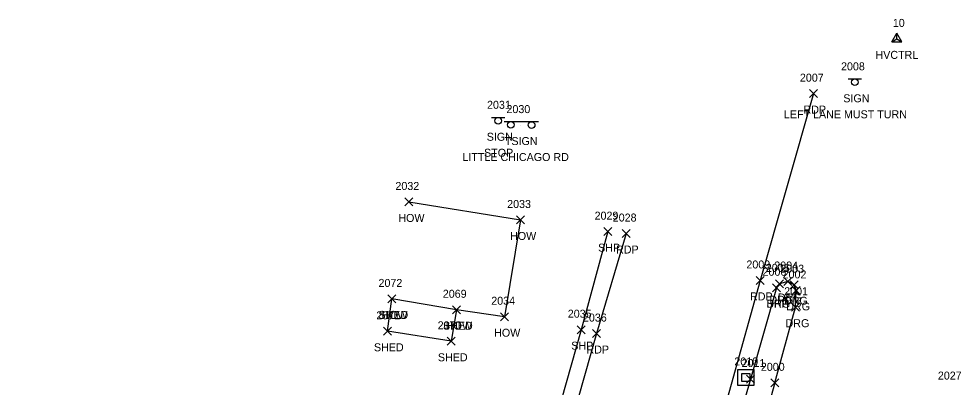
# Model space of a CAD drawing. Extents: x 1443071 to 1445292, y 614024 to 622563.
# Drawn here: x 1444555.8 to 1444791.3, y 622470.6 to 622562.9 of the extents above; entities that cross this region are included whole.
import ezdxf

# ---------------------------------------------------------------- set-up
doc = ezdxf.new("R2010")
doc.units = 0
for name, color, linetype in [('C_A', 7, 'Continuous'), ('C_I', 7, 'Continuous'), ('CPSM', 7, 'Continuous'), ('D_I', 7, 'Continuous'), ('DS', 7, 'Continuous'), ('L_A', 7, 'Continuous'), ('L_I', 7, 'Continuous'), ('L_TIC', 7, 'Continuous'), ('LBC', 7, 'Continuous'), ('P_A', 7, 'Continuous'), ('P_I', 7, 'Continuous'), ('P_TIC', 7, 'Continuous'), ('PET', 7, 'Continuous'), ('PSP', 7, 'Continuous'), ('R_A', 7, 'Continuous'), ('R_I', 7, 'Continuous'), ('R_TIC', 7, 'Continuous'), ('RDG', 7, 'Continuous'), ('S_A', 7, 'Continuous'), ('S_C', 7, 'Continuous'), ('S_I', 7, 'Continuous'), ('SSGN', 7, 'Continuous')]:
    doc.layers.add(name, color=color, linetype=linetype)

msp = doc.modelspace()

# ---------------------------------------------------------------- linework, layer by layer
at = {"layer": 'CPSM'}
for p, q in [((1444773.97, 622557.11), (1444775.22, 622559.27)), ((1444773.97, 622557.11), (1444775.22, 622557.83)), ((1444776.47, 622557.11), (1444775.22, 622559.27)), ((1444775.22, 622557.83), (1444775.22, 622559.27)), ((1444775.22, 622557.83), (1444775.22, 622557.83)), ((1444775.22, 622557.83), (1444776.47, 622557.11)), ((1444773.97, 622557.11), (1444776.47, 622557.11))]:
    msp.add_line(p, q, dxfattribs=at)
at = {"layer": 'DS'}
for p, q in [((1444735.49, 622475.09), (1444739.49, 622475.09)), ((1444735.49, 622471.09), (1444735.49, 622475.09)), ((1444736.49, 622472.09), (1444736.49, 622474.09)), ((1444736.49, 622474.09), (1444738.49, 622474.09)), ((1444737.5, 622473.09), (1444737.5, 622473.09)), ((1444737.5, 622473.09), (1444737.5, 622473.09)), ((1444738.49, 622474.09), (1444738.49, 622472.09)), ((1444739.49, 622475.09), (1444739.49, 622471.09)), ((1444739.49, 622471.09), (1444735.49, 622471.09)), ((1444738.49, 622472.09), (1444736.49, 622472.09))]:
    msp.add_line(p, q, dxfattribs=at)
at = {"layer": 'L_TIC'}
for points in [[(1444652.28, 622516.01), (1444654.28, 622518.01)], [(1444654.28, 622516.01), (1444652.28, 622518.01)], [(1444680.2, 622511.5), (1444682.2, 622513.5)], [(1444682.2, 622511.5), (1444680.2, 622513.5)], [(1444648.05, 622491.74), (1444650.05, 622493.74)], [(1444650.05, 622491.74), (1444648.05, 622493.74)], [(1444648.05, 622491.74), (1444650.05, 622493.74)], [(1444650.05, 622491.74), (1444648.05, 622493.74)], [(1444664.18, 622489.03), (1444666.18, 622491.03)], [(1444666.18, 622489.03), (1444664.18, 622491.03)], [(1444664.18, 622489.03), (1444666.18, 622491.03)], [(1444666.18, 622489.03), (1444664.18, 622491.03)], [(1444676.23, 622487.28), (1444678.23, 622489.28)], [(1444678.23, 622487.28), (1444676.23, 622489.28)], [(1444646.93, 622483.63), (1444648.93, 622485.63)], [(1444648.93, 622483.63), (1444646.93, 622485.63)], [(1444662.91, 622481.13), (1444664.91, 622483.13)], [(1444664.91, 622481.13), (1444662.91, 622483.13)]]:
    msp.add_lwpolyline(points, dxfattribs=at)
at = {"layer": 'LBC'}
for points in [[(1444653.28, 622517.01), (1444681.2, 622512.5), (1444677.23, 622488.28), (1444665.18, 622490.03), (1444649.05, 622492.74)], [(1444665.18, 622490.03), (1444663.91, 622482.13), (1444647.93, 622484.63), (1444649.05, 622492.74)]]:
    msp.add_lwpolyline(points, dxfattribs=at)
at = {"layer": 'P_TIC'}
for points in [[(1444753.44, 622543.13), (1444755.44, 622545.13)], [(1444755.44, 622543.13), (1444753.44, 622545.13)], [(1444702.05, 622508.58), (1444704.05, 622510.58)], [(1444704.05, 622508.58), (1444702.05, 622510.58)], [(1444706.59, 622508.11), (1444708.59, 622510.11)], [(1444708.59, 622508.11), (1444706.59, 622510.11)], [(1444740.07, 622496.37), (1444742.07, 622498.37)], [(1444742.07, 622496.37), (1444740.07, 622498.37)], [(1444744.15, 622494.54), (1444746.15, 622496.54)], [(1444746.15, 622494.54), (1444744.15, 622496.54)], [(1444695.35, 622484.04), (1444697.35, 622486.04)], [(1444697.35, 622484.04), (1444695.35, 622486.04)], [(1444699.19, 622483.07), (1444701.19, 622485.07)], [(1444701.19, 622483.07), (1444699.19, 622485.07)], [(1444737.65, 622471.69), (1444739.65, 622473.69)], [(1444739.65, 622471.69), (1444737.65, 622473.69)]]:
    msp.add_lwpolyline(points, dxfattribs=at)
at = {"layer": 'PET'}
for points in [[(1444754.44, 622544.13), (1444741.07, 622497.37), (1444724.21, 622436.63), (1444710.62, 622388.87), (1444697.45, 622342.15), (1444675, 622264.13), (1444650.85, 622183.92), (1444630.28, 622116), (1444610.88, 622049.25), (1444594.96, 621996.24), (1444563.37, 621884.27), (1444533.4, 621779.05), (1444495.09, 621640.86), (1444437.04, 621433.18), (1444409.83, 621332.84), (1444393.99, 621275.61), (1444360.23, 621155.32)], [(1444707.59, 622509.11), (1444700.19, 622484.07), (1444679.05, 622409.28), (1444655.77, 622327.83), (1444650.07, 622306.66), (1444636.13, 622255.68), (1444623.55, 622208.8), (1444606.26, 622146.53), (1444595.29, 622106.04), (1444582.56, 622060.23), (1444534.43, 621893.79), (1444481.57, 621704.27), (1444439.29, 621553.82), (1444408.11, 621445.28), (1444395.03, 621397.39), (1444367.96, 621301.44), (1444350.41, 621238.76), (1444319.14, 621126.97)]]:
    msp.add_lwpolyline(points, dxfattribs=at)
at = {"layer": 'PSP'}
for points in [[(1444703.05, 622509.58), (1444696.35, 622485.04), (1444679.96, 622426.95), (1444670.67, 622398.4), (1444651.65, 622328.99), (1444645.77, 622309.01), (1444600.31, 622147.99), (1444589.19, 622108.06), (1444575.49, 622063.15), (1444529.28, 621895.39), (1444476.53, 621706.36), (1444455.46, 621630.82), (1444442.09, 621578.45), (1444424.77, 621519.75), (1444412.09, 621475.26), (1444390.88, 621397.93), (1444363.76, 621301.82), (1444345.99, 621239.2), (1444324.65, 621163.68)], [(1444745.15, 622495.54), (1444738.65, 622472.69), (1444728.21, 622436.2), (1444714.89, 622387.13), (1444701.45, 622339.69), (1444679.77, 622260.17), (1444671.12, 622229.57), (1444657.52, 622182.26), (1444644.19, 622133.53), (1444626.95, 622072.43), (1444608.5, 622007.83), (1444599.1, 621977.5), (1444572.99, 621881.76), (1444551.74, 621805.05), (1444541.41, 621769.53), (1444519.46, 621688.51), (1444505.68, 621638.77), (1444452.32, 621450.13), (1444441.68, 621411.27), (1444418.22, 621330.76), (1444405.98, 621283.95), (1444397.04, 621252.99), (1444383.69, 621203.04)]]:
    msp.add_lwpolyline(points, dxfattribs=at)
at = {"layer": 'R_TIC'}
for points in [[(1444744.15, 622494.54), (1444746.15, 622496.54)], [(1444746.15, 622494.54), (1444744.15, 622496.54)], [(1444744.91, 622495.52), (1444746.91, 622497.52)], [(1444746.91, 622495.52), (1444744.91, 622497.52)], [(1444747.03, 622496.1), (1444749.03, 622498.1)], [(1444749.03, 622496.1), (1444747.03, 622498.1)], [(1444748.55, 622495.29), (1444750.55, 622497.29)], [(1444750.55, 622495.29), (1444748.55, 622497.29)], [(1444749.11, 622493.88), (1444751.11, 622495.88)], [(1444751.11, 622493.88), (1444749.11, 622495.88)], [(1444748.94, 622489.66), (1444750.94, 622491.66)], [(1444750.94, 622489.66), (1444748.94, 622491.66)], [(1444743.76, 622470.74), (1444745.76, 622472.74)], [(1444745.76, 622470.74), (1444743.76, 622472.74)], [(1444743.76, 622470.74), (1444745.76, 622472.74)], [(1444745.76, 622470.74), (1444743.76, 622472.74)]]:
    msp.add_lwpolyline(points, dxfattribs=at)
at = {"layer": 'RDG'}
for points in [[(1444744.76, 622471.74), (1444749.94, 622490.66), (1444750.11, 622494.88), (1444749.55, 622496.29), (1444748.03, 622497.1), (1444745.91, 622496.52), (1444745.15, 622495.54)], [(1444744.76, 622471.74), (1444734.26, 622433.99), (1444721.2, 622386.97), (1444719.26, 622385.03), (1444716.7, 622384.74), (1444714.89, 622387.13)]]:
    msp.add_lwpolyline(points, dxfattribs=at)
at = {"layer": 'SSGN'}
for p, q in [((1444763.09, 622547.81), (1444766.42, 622547.81)), ((1444764.74, 622546.98), (1444764.74, 622546.98)), ((1444673.98, 622538.18), (1444677.31, 622538.18)), ((1444675.62, 622537.35), (1444675.62, 622537.35)), ((1444677.09, 622537.18), (1444685.69, 622537.18)), ((1444681.12, 622536.27), (1444681.12, 622536.27))]:
    msp.add_line(p, q, dxfattribs=at)
for centre in [(1444764.74, 622546.98), (1444675.62, 622537.35), (1444678.76, 622536.34), (1444683.97, 622536.27)]:
    msp.add_circle(centre, 0.833, dxfattribs=at)

# ---------------------------------------------------------------- texts
at = {"layer": 'C_A'}
msp.add_text('HVCTRL', height=2, dxfattribs=at).set_placement((1444769.91, 622552.83))
at = {"layer": 'C_I'}
msp.add_text('10', height=2, dxfattribs=at).set_placement((1444774.24, 622560.83))
at = {"layer": 'D_I'}
msp.add_text('2010', height=2, dxfattribs=at).set_placement((1444734.64, 622476.09))
at = {"layer": 'L_A'}
for s, p in [('HOW', (1444650.67, 622512.01)), ('HOW', (1444678.59, 622507.5)), ('SHED', (1444645.69, 622487.74)), ('HOW', (1444646.44, 622487.74)), ('SHED', (1444661.82, 622485.03)), ('HOW', (1444662.56, 622485.03)), ('HOW', (1444674.61, 622483.28)), ('SHED', (1444644.57, 622479.63)), ('SHED', (1444660.55, 622477.13))]:
    msp.add_text(s, height=2, dxfattribs=at).set_placement(p)
at = {"layer": 'L_I'}
for s, p in [('2032', (1444649.94, 622520.01)), ('2033', (1444677.86, 622515.5)), ('2072', (1444645.71, 622495.74)), ('2072', (1444645.71, 622495.74)), ('2069', (1444661.78, 622493.03)), ('2069', (1444661.78, 622493.03)), ('2034', (1444673.89, 622491.28)), ('2071', (1444645.16, 622487.63)), ('2070', (1444660.49, 622485.13)), ('2027', (1444785.5, 622472.55))]:
    msp.add_text(s, height=2, dxfattribs=at).set_placement(p)
at = {"layer": 'P_A'}
for s, p in [('RDP', (1444751.92, 622539.13)), ('SHP', (1444700.59, 622504.58)), ('RDP', (1444705.08, 622504.11)), ('RDP', (1444738.56, 622492.37)), ('SHP', (1444742.68, 622490.54)), ('SHP', (1444693.88, 622480.04)), ('RDP', (1444697.68, 622479.07))]:
    msp.add_text(s, height=2, dxfattribs=at).set_placement(p)
at = {"layer": 'P_I'}
for s, p in [('2007', (1444751.02, 622547.13)), ('2029', (1444699.71, 622512.58)), ('2028', (1444704.25, 622512.11)), ('2009', (1444737.65, 622500.37)), ('2006', (1444741.68, 622498.54)), ('2035', (1444693.01, 622488.04)), ('2036', (1444696.8, 622487.07)), ('2011', (1444736.45, 622475.69))]:
    msp.add_text(s, height=2, dxfattribs=at).set_placement(p)
at = {"layer": 'R_A'}
for p in [(1444745.52, 622492.1), (1444742.64, 622490.54), (1444743.4, 622491.52), (1444747.04, 622491.29), (1444747.6, 622489.88), (1444747.43, 622485.66)]:
    msp.add_text('DRG', height=2, dxfattribs=at).set_placement(p)
at = {"layer": 'R_I'}
for s, p in [('2005', (1444742.5, 622499.52)), ('2004', (1444744.61, 622500.1)), ('2003', (1444746.13, 622499.29)), ('2006', (1444741.68, 622498.54)), ('2002', (1444746.69, 622497.88)), ('2001', (1444747.09, 622493.66)), ('2000', (1444741.26, 622474.74)), ('2000', (1444741.26, 622474.74))]:
    msp.add_text(s, height=2, dxfattribs=at).set_placement(p)
at = {"layer": 'S_A'}
for s, p in [('SIGN', (1444761.87, 622541.96)), ('SIGN', (1444672.76, 622532.33)), ('TSIGN', (1444677.29, 622531.26))]:
    msp.add_text(s, height=2, dxfattribs=at).set_placement(p)
at = {"layer": 'S_C'}
for s, p in [('LEFT LANE MUST TURN', (1444747.02, 622537.96)), ('STOP', (1444672.09, 622528.33)), ('LITTLE CHICAGO RD', (1444666.68, 622527.26))]:
    msp.add_text(s, height=2, dxfattribs=at).set_placement(p)
at = {"layer": 'S_I'}
for s, p in [('2008', (1444761.3, 622549.96)), ('2031', (1444672.83, 622540.33)), ('2030', (1444677.69, 622539.26))]:
    msp.add_text(s, height=2, dxfattribs=at).set_placement(p)

doc.saveas('drawing.dxf')
